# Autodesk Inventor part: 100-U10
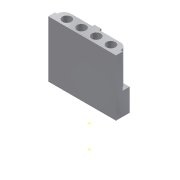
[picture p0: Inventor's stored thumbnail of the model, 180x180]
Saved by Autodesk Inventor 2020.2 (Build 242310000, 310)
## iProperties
GlobalPropertyList: <PropertyList/>
Manager: www.cadconsulting.pl
Company: Fabian Stasiak CAD Consulting
Created: 2014-09
Part Number: 100-U10
Material: Tworzywo sztuczne ABS
Document SubType Name: Modeling
Designer: F.Stasiak
Density: 1.06 g/cm^3
Appearance: Gładki - biały
Categories: <MemberInstance><Categories><Category DisplayName="" Mnemonic="CABLEANDHARNESS" InternalName="e4a7e005-5e42-4d16-b293-125e7f0d0512"><Category DisplayName="" Mne
Catalog Web Link: www.expertbooks.pl
Author: F.Stasiak
Subject: Zbiór ćwiczeń. Autodesk Inventor 2020. Kurs Professional
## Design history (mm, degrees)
sketch "Szkic1"
  geometry: L1 (-15, 3)-(15, 3); L2 (15, 3)-(15, -3); L3 (15, -3)-(-15, -3); L4 (-15, -3)-(-15, 3); L5 (-15, 3)-(15, -3); L6 (15, 3)-(-15, -3); 1 further point
  constraints: 12 end point, 2 midpoint, 2 parallel, 1 horizontal, 1 perpendicular
  dimensions: "d0" = 30 distance of L2.end L3.end; "d1" = 6 distance of L1.end L2.end
extrude "Wyciągnięcie proste1" new body sketch "Szkic1" distance "d2" = 25; taper "d3" = 0 deg
sketch "Szkic2"
  geometry: L1 (15, 3)-(-15, 3) reference; L2 (-15, 3)-(-15, -3) reference; L3 (-15, -3)-(15, -3) reference; L4 (15, -3)-(15, 3) reference; L5 (-15, 3)-(-15, -3) reference; L6 (-15, 0)-(-14, 0); L7 (15, 0)-(14, 0); A1 r 3 centre (-11, 0) between (-11, 3) and (-14, 0); A2 r 3 centre (11, 0) between (14, 0) and (11, 3); 1 further point
  constraints: 4 end point, 4 point on circle, 4 point on line, 2 centre point, 2 horizontal, 2 midpoint
  dimensions: "d4" = 1 distance of L6.start L6.end; "d5" = 3 radius of A1; "d6" = 1 distance of L7.start L7.end; "d7" = 3 radius of A2 (= d5)
extrude "Wyciągnięcie proste2" cut sketch "Szkic2" distance "d8" = 15; taper "d9" = 0 deg
sketch "Szkic3"
  geometry: L1 (-1.5, 2)-(1.5, 2); L2 (1.5, 2)-(1.5, 4); L3 (1.5, 4)-(-1.5, 4); L4 (-1.5, 4)-(-1.5, 2); L5 (11, 3)-(-11, 3) reference; L6 (-1.5, 2)-(1.5, 4); L7 (1.5, 2)-(-1.5, 4); 2 further points
  constraints: 12 end point, 3 midpoint, 2 parallel, 1 horizontal, 1 perpendicular
  dimensions: "d10" = 3 distance of L3.end L2.end; "d11" = 2 distance of L2.end L1.end
extrude "Wyciągnięcie proste3" join sketch "Szkic3" distance "d12" = 15; taper "d13" = 0 deg
sketch "Szkic4"
  geometry: L1 (-14, 0)-(14, 0); L2 (-3.25, 0)-(3.25, 0); C1 r 2 at (-9.75, 0); C2 r 2 at (-3.25, 0); C3 r 2 at (3.25, 0); C4 r 2 at (9.75, 0); 2 further points
  constraints: 4 centre point, 4 end point, 4 point on line, 3 equal radius, 2 horizontal, 2 midpoint
  dimensions: "d14" = 4 diameter of C1; "d15" = 6.5 distance of L2.end L2.start; "d16" = 6.5 distance of L2.start C1.centre; "d17" = 6.5 distance of C4.centre L2.end
extrude "Wyciągnięcie proste4" cut sketch "Szkic4" extent not by distance; stored distance "d18" = 15; taper "d19" = 0 deg
node "Płaszczyzna konstrukcyjna1"
node "Płaszczyzna konstrukcyjna3"
node "Punkt konstrukcyjny5"
node "Punkt konstrukcyjny6"
sketch "Szkic5"
  geometry: C1 r 2 at (-9.75, 0) reference
node "1"
sketch "Szkic6"
  geometry: C1 r 2 at (-3.25, 0) reference
node "2"
sketch "Szkic7"
  geometry: C1 r 2 at (3.25, 0) reference
node "3"
sketch "Szkic8"
  geometry: C1 r 2 at (9.75, 0) reference
node "4"
node "Bryła1"
node "Pętla rzutowana1"
